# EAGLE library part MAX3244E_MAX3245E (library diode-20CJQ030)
Maxim's MAX3224-MAX3245 ±15kV ESD-Protected, 1?A, 1Mbps, 3.0V to 5.5V, RS-232 Transceivers with AutoShutdown Plus Description: The MAX3224E/MAX3225E/MAX3226E/MAX3227E/ MAX3244E/MAX3245E are 3V-powered EIA/TIA-232 and V.28/V.24 communications interfaces with automatic shutdown/wakeup features, high data-rate capabilities, and enhanced electrostatic discharge (ESD) protection. All transmitter outputs and receiver inputs are protected to ±15kV using IEC 1000-4-2 Air-Gap Discharge, ±8kV using IEC 1000-4-2 Contact Discharge, and ±15kV using the Human Body Model. All devices achieve a 1µA supply current using Maxim's revolutionary AutoShutdown Plus feature. These devices automatically enter a low-power shutdown mode when the RS-232 cable is disconnected or the transmitters of the connected peripherals are inactive, and the UART driving the transmitter inputs is inactive for more than 30 seconds. They turn on again when they sense a valid transition at any transmitter or receiver input. AutoShutdown Plus saves power without hanges to the existing BIOS or operating system. The MAX3225E/MAX3227E/MAX3245E also feature MegaBaud oper ation, guaranteeing 1Mbps for highspeed applications such as communicating with ISDN modems. The MAX3224E/MAX3226E/MAX3244E guarantee 250kbps operation. The transceivers have a proprietary low-dropout transmitter output stage enabling true RS-232 performance from a +3.0V to +5.5V supply with a dual charge pump. The charge pump requires only four small 0.1µF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
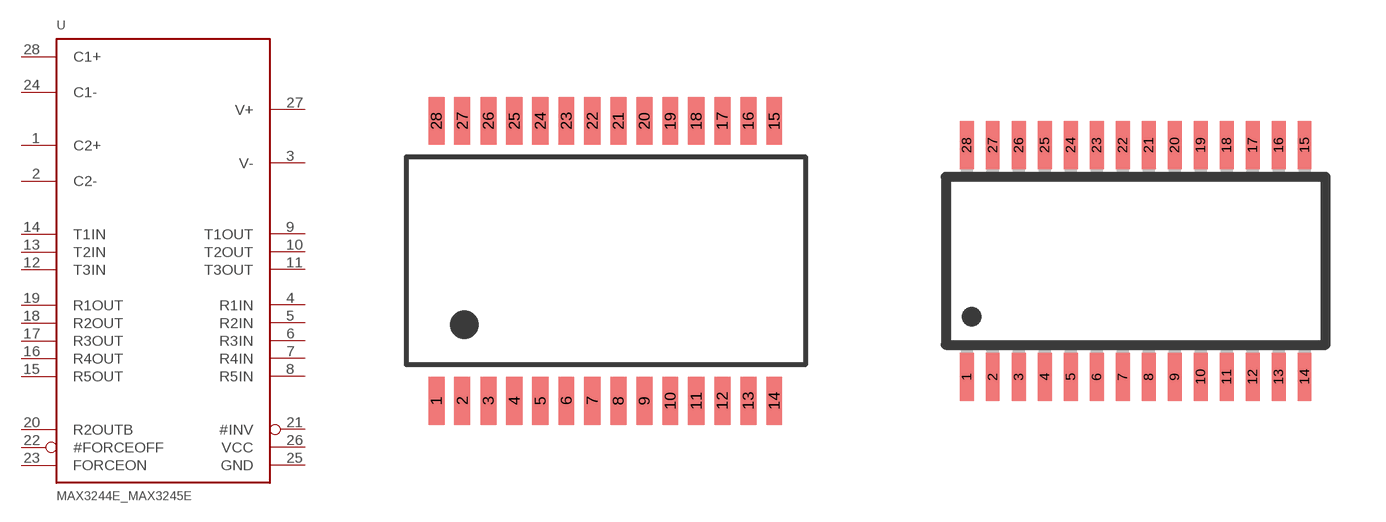
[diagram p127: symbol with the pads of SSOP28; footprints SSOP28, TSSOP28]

Designator prefix U

## MAX3244E_MAX3245ECAI  [SSOP28]
1  C2+  in
2  C2-  in
3  V-
4  R1IN  in
5  R2IN  in
6  R3IN  in
7  R4IN  in
8  R5IN  in
9  T1OUT  out
10  T2OUT  out
11  T3OUT  out
12  T3IN  in
13  T2IN  in
14  T1IN  in
15  R5OUT  out
16  R4OUT  out
17  R3OUT  out
18  R2OUT  out
19  R1OUT  out
20  R2OUTB  out
21  #INV  out
22  #FORCEOFF  in
23  FORCEON  in
24  C1-  in
25  GND  pwr
26  VCC  pwr
27  V+
28  C1+  in

## MAX3244E_MAX3245ECUI  [TSSOP28]
Pads as for SSOP28

## Footprint SSOP28 (pad centres in mm)
SSOP-28 Package E.g. LTC1628
smd 0.4 x 1.2: 1 -4.225,-3.5; 2 -3.575,-3.5; 3 -2.925,-3.5; 4 -2.275,-3.5; 5 -1.625,-3.5; 6 -0.975,-3.5; 7 -0.325,-3.5; 8 0.325,-3.5; 9 0.975,-3.5; 10 1.625,-3.5; 11 2.275,-3.5; 12 2.925,-3.5; 13 3.575,-3.5; 14 4.225,-3.5; 15 4.225,3.5; 16 3.575,3.5; 17 2.925,3.5; 18 2.275,3.5; 19 1.625,3.5; 20 0.975,3.5; 21 0.325,3.5; 22 -0.325,3.5; 23 -0.975,3.5; 24 -1.625,3.5; 25 -2.275,3.5; 26 -2.925,3.5; 27 -3.575,3.5; 28 -4.225,3.5

## Footprint TSSOP28 (pad centres in mm)
28-Lead TSSOP Package RU-28
smd 0.35 x 1.2: 1 -4.225,-2.9; 2 -3.575,-2.9; 3 -2.925,-2.9; 4 -2.275,-2.9; 5 -1.625,-2.9; 6 -0.975,-2.9; 7 -0.325,-2.9; 8 0.325,-2.9; 9 0.975,-2.9; 10 1.625,-2.9; 11 2.275,-2.9; 12 2.925,-2.9; 13 3.575,-2.9; 14 4.225,-2.9; 15 4.225,2.9; 16 3.575,2.9; 17 2.925,2.9; 18 2.275,2.9; 19 1.625,2.9; 20 0.975,2.9; 21 0.325,2.9; 22 -0.325,2.9; 23 -0.975,2.9; 24 -1.625,2.9; 25 -2.275,2.9; 26 -2.925,2.9; 27 -3.575,2.9; 28 -4.225,2.9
